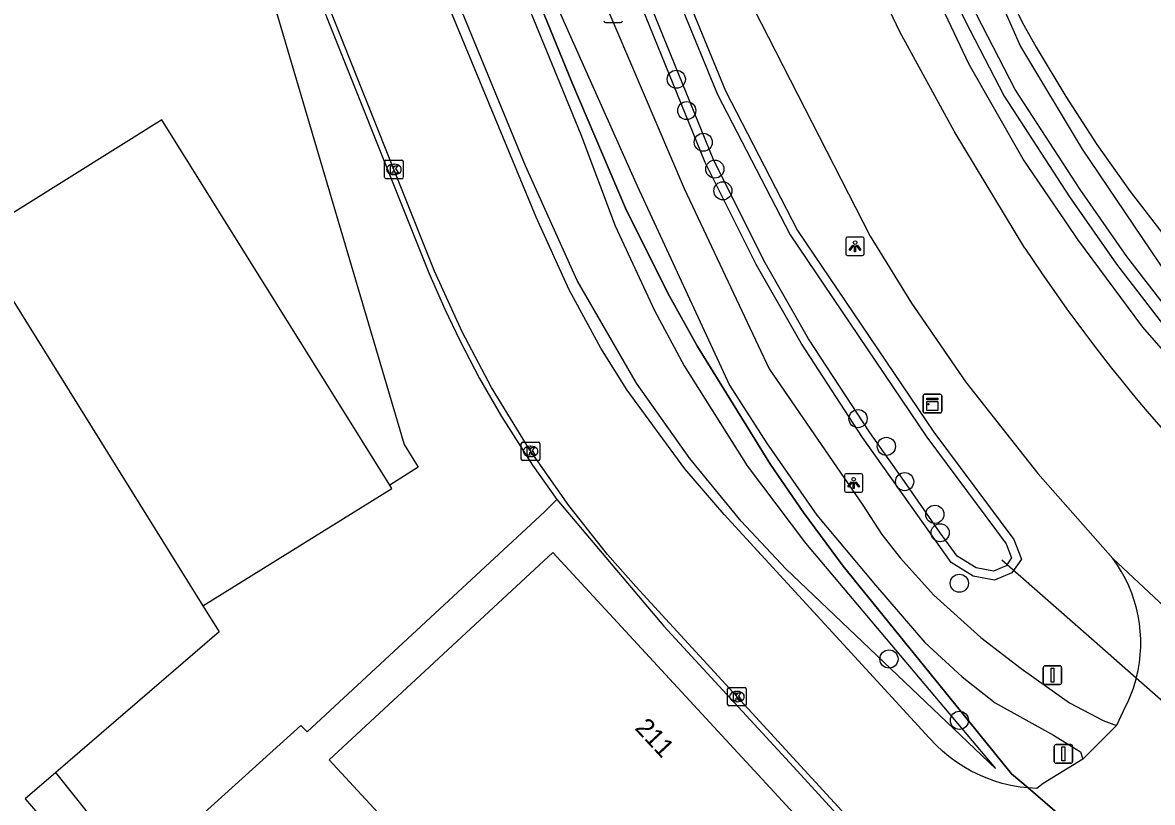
# Model space of a CAD drawing. Extents: x 156061 to 157804, y 383451 to 385640.
# Drawn here: x 157607.5 to 157668.4, y 383669.5 to 383711.6 of the extents above; entities that cross this region are included whole.
import ezdxf

# ---------------------------------------------------------------- set-up
doc = ezdxf.new("R2010")
doc.units = 0
for name, color, linetype in [('IMGEO_Berm_groen', 7, 'Continuous'), ('IMGEO_Boom', 7, 'Continuous'), ('IMGEO_Duiker', 7, 'Continuous'), ('IMGEO_Fietspad_gesloten', 7, 'Continuous'), ('IMGEO_Gemengd_bos', 7, 'Continuous'), ('IMGEO_Grasland_overig', 7, 'Continuous'), ('IMGEO_Groenvoorziening', 7, 'Continuous'), ('IMGEO_Hek', 7, 'Continuous'), ('IMGEO_Kast', 7, 'Continuous'), ('IMGEO_Kolk', 7, 'Continuous'), ('IMGEO_Lichtpunt', 7, 'Continuous'), ('IMGEO_Pand', 7, 'Continuous'), ('IMGEO_Pand_nummerreeks', 7, 'Continuous'), ('IMGEO_Rijbaan_lokaal_gesloten', 7, 'Continuous'), ('IMGEO_Rijbaan_lokaal_open', 7, 'Continuous'), ('IMGEO_Verkeersbordpaal', 7, 'Continuous'), ('IMGEO_Waterloop', 7, 'Continuous')]:
    doc.layers.add(name, color=color, linetype=linetype)

msp = doc.modelspace()

# ---------------------------------------------------------------- linework, layer by layer
at = {"layer": 'IMGEO_Berm_groen'}
msp.add_lwpolyline([(157656.632, 383689.474), (157660.937, 383683.676), (157661.345, 383682.627), (157660.835, 383681.881), (157659.893, 383681.496), (157658.745, 383681.699), (157657.555, 383682.443), (157652.785, 383689.179), (157649.474, 383694.263), (157647.042, 383698.509), (157644.296, 383704.009), (157630.634, 383737.612), (157621.052, 383760.833), (157597.456, 383819.12), (157599.565, 383819.919), (157622.01, 383766.684), (157628.75, 383750), (157632.796, 383738.492), (157645.394, 383707.875), (157649.283, 383700.352), (157656.632, 383689.474)], dxfattribs=at)
at = {"layer": 'IMGEO_Boom'}
for centre in [(157642.74, 383708.502), (157643.304, 383706.811), (157644.195, 383705.104), (157644.818, 383703.657), (157645.254, 383702.485), (157652.54, 383690.2), (157654.069, 383688.702), (157655.052, 383686.803), (157656.682, 383685.039), (157656.967, 383684.044), (157658.002, 383681.323), (157654.208, 383677.236), (157658.006, 383673.93)]:
    msp.add_circle(centre, 0.489, dxfattribs=at)
at = {"layer": 'IMGEO_Duiker'}
msp.add_lwpolyline([(157680.128, 383665.155), (157679.878, 383665.374), (157673.509, 383670.965), (157667.541, 383676.205), (157665.124, 383678.326), (157660.298, 383682.563)], dxfattribs=at)
at = {"layer": 'IMGEO_Fietspad_gesloten'}
for points in [[(157619.12, 383759.995), (157619.272, 383759.605), (157619.425, 383759.216), (157621.18, 383754.837), (157623.144, 383750), (157627.643, 383739.156), (157638.747, 383712.974), (157643.168, 383702.614), (157647.755, 383692.88), (157652.793, 383685.539), (157653.818, 383683.942), (157654.817, 383682.694), (157656.624, 383680.676), (157659.165, 383678.4), (157661.336, 383676.722), (157663.95, 383674.865), (157665.764, 383673.914), (157666.48, 383673.644)], [(157617.209, 383759.165), (157617.337, 383758.839), (157617.465, 383758.512), (157619.121, 383754.329), (157620.857, 383750), (157625.641, 383738.364), (157636.444, 383712.133), (157640.636, 383702.745), (157645.615, 383692.003), (157647.612, 383688.893), (157650.31, 383684.991), (157653.473, 383681.227), (157656.137, 383678.12), (157658.153, 383676.273), (157659.933, 383674.868), (157663.084, 383673.125), (157664.534, 383672.23), (157664.66, 383671.828)]]:
    msp.add_lwpolyline(points, dxfattribs=at)
at = {"layer": 'IMGEO_Gemengd_bos'}
msp.add_lwpolyline([(157636.229, 383767.455), (157638.156, 383768.256), (157645.652, 383750), (157659.252, 383715.786), (157661.478, 383711.421), (157662.149, 383710.223), (157663.736, 383707.568), (157665.424, 383704.976), (157667.211, 383702.452), (157669.095, 383699.999), (157669.464, 383699.533), (157671.499, 383697.085), (157673.624, 383694.715), (157675.836, 383692.426), (157678.134, 383690.223), (157680.513, 383688.108), (157682.97, 383686.083), (157685.501, 383684.153), (157688.104, 383682.32), (157690.773, 383680.586), (157691.823, 383679.959)], dxfattribs=at)
at = {"layer": 'IMGEO_Grasland_overig'}
for points in [[(157622.915, 383714.315), (157620.719, 383713.705), (157628.075, 383688.812), (157628.823, 383687.576), (157627.287, 383686.608)], [(157636.298, 383685.833), (157635.64, 383685.18), (157622.846, 383673.301), (157622.498, 383673.653), (157617.28, 383668.944), (157624.23, 383661.417), (157624.003, 383661.197)], [(157617.211, 383680.099), (157618.102, 383678.709), (157609.282, 383671.12)], [(157609.282, 383671.12), (157607.636, 383669.704), (157608.419, 383668.784), (157618.847, 383656.716), (157619.968, 383657.726)], [(157619.968, 383657.726), (157609.282, 383671.12)]]:
    msp.add_lwpolyline(points, dxfattribs=at)
at = {"layer": 'IMGEO_Groenvoorziening'}
for points in [[(157591.436, 383820.144), (157616.353, 383759.165), (157616.482, 383758.849), (157620.09, 383750), (157637.106, 383708.345), (157640.011, 383701.544), (157642.293, 383696.97), (157643.878, 383694.087), (157647.814, 383687.72), (157649.591, 383685.145), (157651.737, 383682.237), (157660.817, 383671.051), (157661.711, 383670.281)], [(157659.948, 383671.324), (157648.645, 383682.101), (157646.245, 383684.678), (157643.471, 383688.052), (157640.601, 383692.115), (157637.39, 383697.645), (157634.608, 383703.827), (157615.621, 383750), (157589.147, 383814.382), (157590.971, 383816.65), (157608.011, 383777.219), (157619.357, 383750), (157637.598, 383705.528), (157639.454, 383700.6), (157641.568, 383696.029), (157643.168, 383693.05), (157646.562, 383687.66), (157649.7, 383683.481), (157659.948, 383671.324)], [(157636.229, 383767.455), (157653.276, 383727.674), (157657.983, 383717.796), (157661.304, 383710.272), (157664.631, 383704.734), (157669.217, 383697.917)], [(157672.252, 383690.146), (157667.892, 383695.128), (157664.393, 383699.858), (157664.241, 383700.081), (157661.436, 383704.196), (157658.535, 383709.296), (157648.992, 383729.466), (157633.995, 383766.54)]]:
    msp.add_lwpolyline(points, dxfattribs=at)
at = {"layer": 'IMGEO_Hek'}
for points in [[(157661.711, 383670.281), (157660.817, 383671.051), (157651.737, 383682.237), (157649.591, 383685.145), (157647.814, 383687.72), (157643.878, 383694.087), (157642.293, 383696.97), (157640.011, 383701.544), (157637.106, 383708.345), (157620.09, 383750)], [(157667.614, 383665.197), (157661.711, 383670.281)]]:
    msp.add_lwpolyline(points, dxfattribs=at)
at = {"layer": 'IMGEO_Kast'}
for p, q in [((157656.052, 383690.585), (157656.052, 383691.426)), ((157656.052, 383691.426), (157656.052, 383690.585)), ((157656.127, 383691.51), (157656.968, 383691.51)), ((157656.968, 383691.51), (157656.127, 383691.51)), ((157657.052, 383691.435), (157657.052, 383690.594)), ((157657.052, 383690.594), (157657.052, 383691.435)), ((157656.977, 383690.51), (157656.136, 383690.51)), ((157656.136, 383690.51), (157656.977, 383690.51))]:
    msp.add_line(p, q, dxfattribs=at)
for points in [[(157656.247, 383691.3), (157656.847, 383691.3), (157656.847, 383691.215), (157656.247, 383691.215), (157656.247, 383691.3)], [(157656.247, 383691.125), (157656.847, 383691.125), (157656.847, 383690.636), (157656.247, 383690.636), (157656.247, 383691.125)]]:
    msp.add_lwpolyline(points, dxfattribs=at)
msp.add_circle((157656.331, 383690.974), 0.0377, dxfattribs=at)
for centre, start, end in [((157656.13, 383691.432), 92.4484, 184.28452), ((157656.13, 383691.432), 92.4484, 184.28452), ((157656.974, 383691.432), 2.4484, 94.28452), ((157656.974, 383691.432), 2.4484, 94.28452), ((157656.13, 383690.588), 182.4484, 274.28452), ((157656.13, 383690.588), 182.4484, 274.28452), ((157656.974, 383690.588), 272.4484, 4.28452), ((157656.974, 383690.588), 272.4484, 4.28452)]:
    msp.add_arc(centre, 0.0779, start, end, dxfattribs=at)
at = {"layer": 'IMGEO_Kolk'}
for p, q in [((157627.013, 383703.212), (157627.013, 383704.064)), ((157627.088, 383704.138), (157627.94, 383704.138)), ((157627.501, 383703.918), (157627.526, 383703.918)), ((157628.014, 383704.064), (157628.014, 383703.212)), ((157627.524, 383703.358), (157627.499, 383703.358)), ((157627.94, 383703.138), (157627.088, 383703.138)), ((157634.382, 383688.008), (157634.382, 383688.86)), ((157634.457, 383688.934), (157635.309, 383688.934)), ((157634.87, 383688.714), (157634.895, 383688.714)), ((157635.383, 383688.86), (157635.383, 383688.008)), ((157635.309, 383687.934), (157634.457, 383687.934)), ((157634.893, 383688.154), (157634.868, 383688.154)), ((157645.507, 383674.782), (157645.507, 383675.634)), ((157645.582, 383675.708), (157646.434, 383675.708)), ((157645.995, 383675.488), (157646.02, 383675.488)), ((157646.508, 383675.634), (157646.508, 383674.782)), ((157646.434, 383674.708), (157645.582, 383674.708)), ((157646.018, 383674.928), (157645.993, 383674.928))]:
    msp.add_line(p, q, dxfattribs=at)
for points in [[(157627.013, 383703.212), (157627.013, 383704.064)], [(157627.088, 383704.138), (157627.94, 383704.138)], [(157627.334, 383703.838), (157627.457, 383703.838), (157627.457, 383703.687), (157627.587, 383703.838), (157627.751, 383703.838), (157627.605, 383703.687), (157627.758, 383703.438), (157627.606, 383703.438), (157627.521, 383703.602), (157627.457, 383703.535), (157627.457, 383703.438), (157627.334, 383703.438), (157627.334, 383703.838)], [(157628.014, 383704.064), (157628.014, 383703.212)], [(157627.94, 383703.138), (157627.088, 383703.138)], [(157634.382, 383688.008), (157634.382, 383688.86)], [(157634.457, 383688.934), (157635.309, 383688.934)], [(157634.703, 383688.634), (157634.826, 383688.634), (157634.826, 383688.483), (157634.956, 383688.634), (157635.12, 383688.634), (157634.974, 383688.483), (157635.127, 383688.234), (157634.975, 383688.234), (157634.89, 383688.398), (157634.826, 383688.331), (157634.826, 383688.234), (157634.703, 383688.234), (157634.703, 383688.634)], [(157635.383, 383688.86), (157635.383, 383688.008)], [(157635.309, 383687.934), (157634.457, 383687.934)], [(157645.507, 383674.782), (157645.507, 383675.634)], [(157645.582, 383675.708), (157646.434, 383675.708)], [(157645.828, 383675.408), (157645.951, 383675.408), (157645.951, 383675.257), (157646.081, 383675.408), (157646.245, 383675.408), (157646.099, 383675.257), (157646.252, 383675.008), (157646.1, 383675.008), (157646.015, 383675.172), (157645.951, 383675.105), (157645.951, 383675.008), (157645.828, 383675.008), (157645.828, 383675.408)], [(157646.508, 383675.634), (157646.508, 383674.782)], [(157646.434, 383674.708), (157645.582, 383674.708)]]:
    msp.add_lwpolyline(points, dxfattribs=at)
for centre, start, end in [((157627.09, 383704.062), 91.55205, 178.44795), ((157627.09, 383704.062), 91.55205, 178.44795), ((157627.938, 383704.062), 1.55205, 88.44795), ((157627.938, 383704.062), 1.55205, 88.44795), ((157627.09, 383703.214), 181.55205, 268.44795), ((157627.09, 383703.214), 181.55205, 268.44795), ((157627.938, 383703.214), 271.55205, 358.44795), ((157627.938, 383703.214), 271.55205, 358.44795), ((157634.459, 383688.858), 91.55205, 178.44795), ((157634.459, 383688.858), 91.55205, 178.44795), ((157635.307, 383688.858), 1.55205, 88.44795), ((157635.307, 383688.858), 1.55205, 88.44795), ((157634.459, 383688.01), 181.55205, 268.44795), ((157634.459, 383688.01), 181.55205, 268.44795), ((157635.307, 383688.01), 271.55205, 358.44795), ((157635.307, 383688.01), 271.55205, 358.44795), ((157645.584, 383675.632), 91.55205, 178.44795), ((157645.584, 383675.632), 91.55205, 178.44795), ((157646.432, 383675.632), 1.55205, 88.44795), ((157646.432, 383675.632), 1.55205, 88.44795), ((157645.584, 383674.784), 181.55205, 268.44795), ((157645.584, 383674.784), 181.55205, 268.44795), ((157646.432, 383674.784), 271.55205, 358.44795), ((157646.432, 383674.784), 271.55205, 358.44795)]:
    msp.add_arc(centre, 0.0765, start, end, dxfattribs=at)
for centre, major_axis, ratio, start_param, end_param in [((157627.5, 383703.638), (-0.387, 0.002), 0.722429, 4.712389, 7.853982), ((157627.525, 383703.638), (-0.39, 0.002), 0.717154, 1.570796, 4.712389), ((157634.869, 383688.434), (-0.387, 0.002), 0.722429, 4.712389, 7.853982), ((157634.894, 383688.434), (-0.39, 0.002), 0.717154, 1.570796, 4.712389), ((157645.994, 383675.208), (-0.387, 0.002), 0.722429, 4.712389, 7.853982), ((157646.019, 383675.208), (-0.39, 0.002), 0.717154, 1.570796, 4.712389)]:
    msp.add_ellipse(centre, major_axis=major_axis, ratio=ratio, start_param=start_param, end_param=end_param, dxfattribs=at)
at = {"layer": 'IMGEO_Lichtpunt'}
for p, q in [((157638.931, 383711.557), (157639.739, 383711.557)), ((157638.931, 383711.557), (157639.739, 383711.557)), ((157651.88, 383699.898), (157651.88, 383699.091)), ((157651.88, 383699.898), (157651.88, 383699.091)), ((157652.782, 383699.993), (157651.974, 383699.993)), ((157652.782, 383699.993), (157651.974, 383699.993)), ((157652.876, 383699.091), (157652.876, 383699.898)), ((157652.876, 383699.091), (157652.876, 383699.898)), ((157651.974, 383698.997), (157652.782, 383698.997)), ((157651.974, 383698.997), (157652.782, 383698.997)), ((157651.804, 383687.133), (157651.804, 383686.326)), ((157651.804, 383687.133), (157651.804, 383686.326)), ((157652.706, 383687.228), (157651.898, 383687.228)), ((157652.706, 383687.228), (157651.898, 383687.228)), ((157652.8, 383686.326), (157652.8, 383687.133)), ((157652.8, 383686.326), (157652.8, 383687.133)), ((157651.898, 383686.232), (157652.706, 383686.232)), ((157651.898, 383686.232), (157652.706, 383686.232))]:
    msp.add_line(p, q, dxfattribs=at)
for points in [[(157652.254, 383699.562), (157652.293, 383699.534), (157652.105, 383699.272), (157652.067, 383699.299), (157652.254, 383699.562)], [(157652.356, 383699.514), (157652.403, 383699.514), (157652.403, 383699.192), (157652.356, 383699.192), (157652.356, 383699.514)], [(157652.466, 383699.534), (157652.504, 383699.561), (157652.691, 383699.299), (157652.652, 383699.271), (157652.466, 383699.534)], [(157652.178, 383686.797), (157652.217, 383686.769), (157652.029, 383686.507), (157651.991, 383686.534), (157652.178, 383686.797)], [(157652.28, 383686.749), (157652.327, 383686.749), (157652.327, 383686.427), (157652.28, 383686.427), (157652.28, 383686.749)], [(157652.39, 383686.769), (157652.428, 383686.796), (157652.615, 383686.534), (157652.576, 383686.506), (157652.39, 383686.769)]]:
    msp.add_lwpolyline(points, dxfattribs=at)
for centre in [(157652.379, 383699.696), (157652.303, 383686.931)]:
    msp.add_circle(centre, 0.0994, dxfattribs=at)
for centre, start, end in [((157638.931, 383711.651), 180, 270), ((157638.931, 383711.651), 180, 270), ((157639.739, 383711.651), 270, 0), ((157639.739, 383711.651), 270, 360), ((157651.974, 383699.898), 90, 180), ((157651.974, 383699.898), 90, 180), ((157652.782, 383699.898), 0, 90), ((157652.782, 383699.898), 0, 90), ((157651.974, 383699.091), 180, 270), ((157651.974, 383699.091), 180, 270), ((157652.782, 383699.091), 270, 0), ((157652.782, 383699.091), 270, 360), ((157651.898, 383687.133), 90, 180), ((157651.898, 383687.133), 90, 180), ((157652.706, 383687.133), 0, 90), ((157652.706, 383687.133), 0, 90), ((157651.898, 383686.326), 180, 270), ((157651.898, 383686.326), 180, 270), ((157652.706, 383686.326), 270, 0), ((157652.706, 383686.326), 270, 360)]:
    msp.add_arc(centre, 0.0946, start, end, dxfattribs=at)
at = {"layer": 'IMGEO_Pand'}
for points in [[(157627.287, 383686.608), (157614.994, 383706.315), (157604.846, 383699.969), (157617.211, 383680.099)], [(157617.211, 383680.099), (157627.398, 383686.431), (157627.287, 383686.608)], [(157639.423, 383655.14), (157635.882, 383658.959), (157636.783, 383659.847), (157628.424, 383668.849), (157627.528, 383668.013), (157624.022, 383671.797), (157636.09, 383682.98), (157637.392, 383681.569), (157651.485, 383666.295), (157639.423, 383655.14)]]:
    msp.add_lwpolyline(points, dxfattribs=at)
at = {"layer": 'IMGEO_Rijbaan_lokaal_gesloten'}
for points in [[(157602.956, 383818.231), (157609.325, 383802.679), (157625.684, 383762.843), (157630.958, 383750), (157641.684, 383723.88), (157646.921, 383712.29), (157653.189, 383700.032), (157655.418, 383696.421), (157658.348, 383692.157), (157662.238, 383687.235), (157666.28, 383682.654)], [(157661.711, 383670.281), (157661.278, 383670.331), (157660.784, 383670.418), (157660.315, 383670.53), (157659.856, 383670.669), (157659.172, 383670.934), (157658.639, 383671.193), (157658.251, 383671.413), (157657.842, 383671.678), (157657.431, 383671.982), (157657.096, 383672.261), (157656.769, 383672.566), (157656.375, 383672.981), (157645.33, 383685.028), (157643.2, 383687.496), (157640.091, 383691.739), (157638.679, 383694.001), (157636.963, 383697.145), (157635.183, 383701.072), (157614.923, 383750), (157588.278, 383814.347)], [(157681.542, 383607.66), (157681.915, 383611.645), (157682.248, 383616.298), (157682.165, 383620.962), (157681.665, 383625.6), (157680.752, 383630.175), (157680.657, 383630.556), (157679.272, 383634.513), (157677.539, 383638.33), (157675.471, 383641.977), (157673.087, 383645.425), (157670.403, 383648.646), (157670.038, 383649.042), (157640.558, 383681.144), (157639.039, 383682.875), (157636.942, 383685.511), (157634.822, 383688.528), (157632.775, 383691.884), (157631.195, 383694.874), (157629.704, 383698.154), (157609.012, 383750), (157585.847, 383808.044)], [(157661.539, 383699.392), (157657.716, 383705.699), (157654.786, 383711.05), (157649.595, 383721.988), (157638.253, 383750), (157631.951, 383765.563), (157630.852, 383768.278)], [(157666.28, 383682.654), (157677.949, 383671.748)], [(157667.541, 383676.205), (157667.375, 383675.651), (157667.128, 383675.025), (157666.827, 383674.423), (157666.48, 383673.644)], [(157666.48, 383673.644), (157664.66, 383671.828)], [(157664.66, 383671.828), (157662.52, 383670.523), (157662.188, 383670.253), (157661.711, 383670.281)], [(157661.711, 383670.281), (157667.614, 383665.197)]]:
    msp.add_lwpolyline(points, dxfattribs=at)
for centre, radius, start, end in [((157737.195, 383749.157), 90.556, 213.33611, 229.48121), ((157660.2, 383678.117), 7.586, 345.39986, 36.72752)]:
    msp.add_arc(centre, radius, start, end, dxfattribs=at)
at = {"layer": 'IMGEO_Rijbaan_lokaal_open'}
for points in [[(157622.915, 383714.315), (157629.402, 383698.056), (157630.259, 383696.094), (157631.063, 383694.413), (157632.13, 383692.372), (157633.31, 383690.317), (157634.986, 383687.693), (157636.298, 383685.833)], [(157636.298, 383685.833), (157642.073, 383679.016), (157649.055, 383671.421), (157652.735, 383667.414), (157663.63, 383655.554)]]:
    msp.add_lwpolyline(points, dxfattribs=at)
at = {"layer": 'IMGEO_Verkeersbordpaal'}
for p, q in [((157662.528, 383675.968), (157662.528, 383676.768)), ((157662.528, 383676.768), (157662.528, 383675.968)), ((157662.628, 383676.868), (157663.418, 383676.868)), ((157663.418, 383676.868), (157662.628, 383676.868)), ((157663.518, 383676.768), (157663.518, 383675.968)), ((157663.518, 383675.968), (157663.518, 383676.768)), ((157663.418, 383675.868), (157662.628, 383675.868)), ((157662.628, 383675.868), (157663.418, 383675.868)), ((157663.117, 383671.718), (157663.117, 383672.518)), ((157663.117, 383672.518), (157663.117, 383671.718)), ((157663.217, 383672.618), (157664.007, 383672.618)), ((157664.007, 383672.618), (157663.217, 383672.618)), ((157664.107, 383672.518), (157664.107, 383671.718)), ((157664.107, 383671.718), (157664.107, 383672.518)), ((157664.007, 383671.618), (157663.217, 383671.618)), ((157663.217, 383671.618), (157664.007, 383671.618))]:
    msp.add_line(p, q, dxfattribs=at)
for points in [[(157662.948, 383676.743), (157663.098, 383676.743), (157663.098, 383675.993), (157662.948, 383675.993), (157662.948, 383676.743)], [(157663.537, 383672.493), (157663.687, 383672.493), (157663.687, 383671.743), (157663.537, 383671.743), (157663.537, 383672.493)]]:
    msp.add_lwpolyline(points, dxfattribs=at)
for centre, start, end in [((157662.628, 383676.768), 90, 180), ((157662.628, 383676.768), 90, 180), ((157663.418, 383676.768), 0, 90), ((157663.418, 383676.768), 360, 90), ((157662.628, 383675.968), 180, 270), ((157662.628, 383675.968), 180, 270), ((157663.418, 383675.968), 270, 0), ((157663.418, 383675.968), 270, 0), ((157663.217, 383672.518), 90, 180), ((157663.217, 383672.518), 90, 180), ((157664.007, 383672.518), 0, 90), ((157664.007, 383672.518), 360, 90), ((157663.217, 383671.718), 180, 270), ((157663.217, 383671.718), 180, 270), ((157664.007, 383671.718), 270, 0), ((157664.007, 383671.718), 270, 0)]:
    msp.add_arc(centre, 0.1, start, end, dxfattribs=at)
at = {"layer": 'IMGEO_Waterloop'}
for points in [[(157659.841, 383681.981), (157658.916, 383682.145), (157657.883, 383682.791), (157656.967, 383684.044), (157655.052, 383686.803), (157653.173, 383689.443), (157649.874, 383694.508), (157647.456, 383698.73), (157644.724, 383704.202), (157631.068, 383737.79), (157628.743, 383743.459), (157627.544, 383746.427), (157621.486, 383761.01), (157619.788, 383765.138), (157618.289, 383768.786)], [(157669.854, 383695.286), (157667.033, 383698.949), (157664.522, 383702.556), (157661.016, 383707.946), (157658.947, 383711.954), (157657.625, 383714.795), (157635.559, 383767.177)], [(157634.876, 383766.897), (157648.738, 383733.202), (157657.467, 383713.475), (157658.318, 383711.646), (157660.412, 383707.591), (157663.94, 383702.167), (157666.468, 383698.535), (157669.31, 383694.845)], [(157621.577, 383766.505), (157628.311, 383749.834), (157632.358, 383738.325), (157644.968, 383707.678), (157648.879, 383700.112), (157656.249, 383689.203), (157660.523, 383683.447), (157660.818, 383682.687), (157660.527, 383682.262), (157659.841, 383681.981)]]:
    msp.add_lwpolyline(points, dxfattribs=at)

# ---------------------------------------------------------------- texts
at = {"layer": 'IMGEO_Pand_nummerreeks'}
msp.add_text('211', height=1, rotation=312.88759, dxfattribs=at).set_placement((157640.464, 383673.477))

doc.saveas('drawing.dxf')
